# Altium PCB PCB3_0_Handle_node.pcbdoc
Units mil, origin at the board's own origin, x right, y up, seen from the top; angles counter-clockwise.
Board outline 4221.61 x 2402.51 mil, 2 copper layers (Top Layer, Bottom Layer), stack 2.757 mil thick; 43 components, 44 nets, 194 pads, 115 vias.
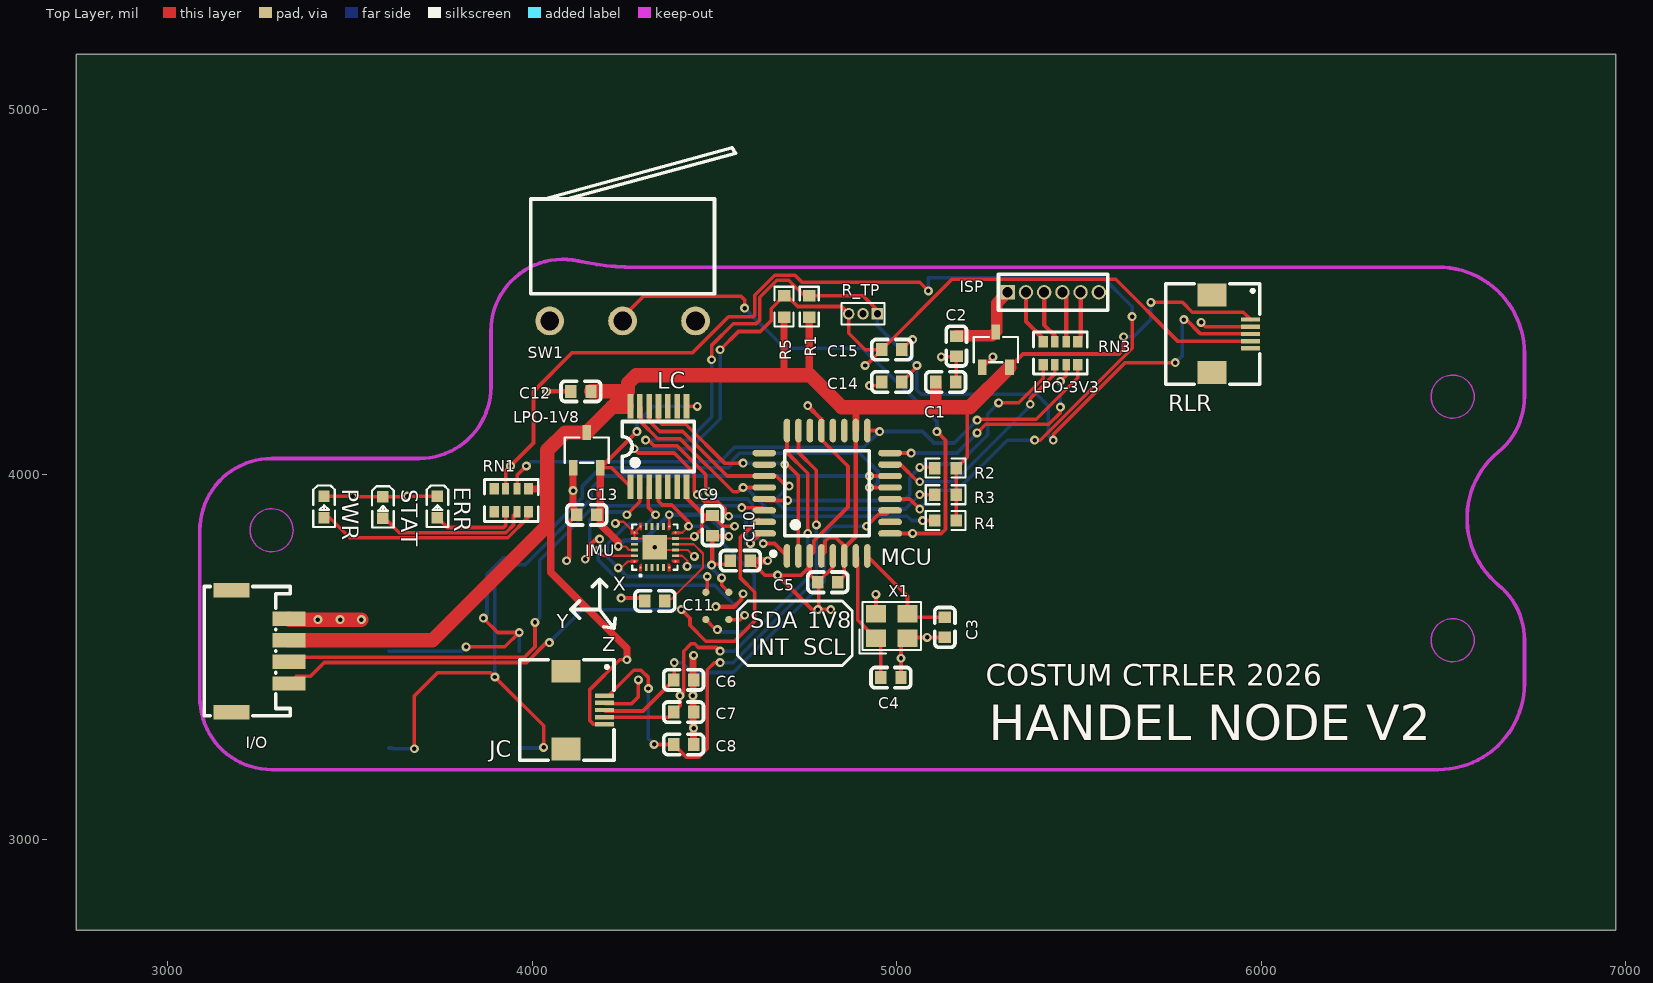
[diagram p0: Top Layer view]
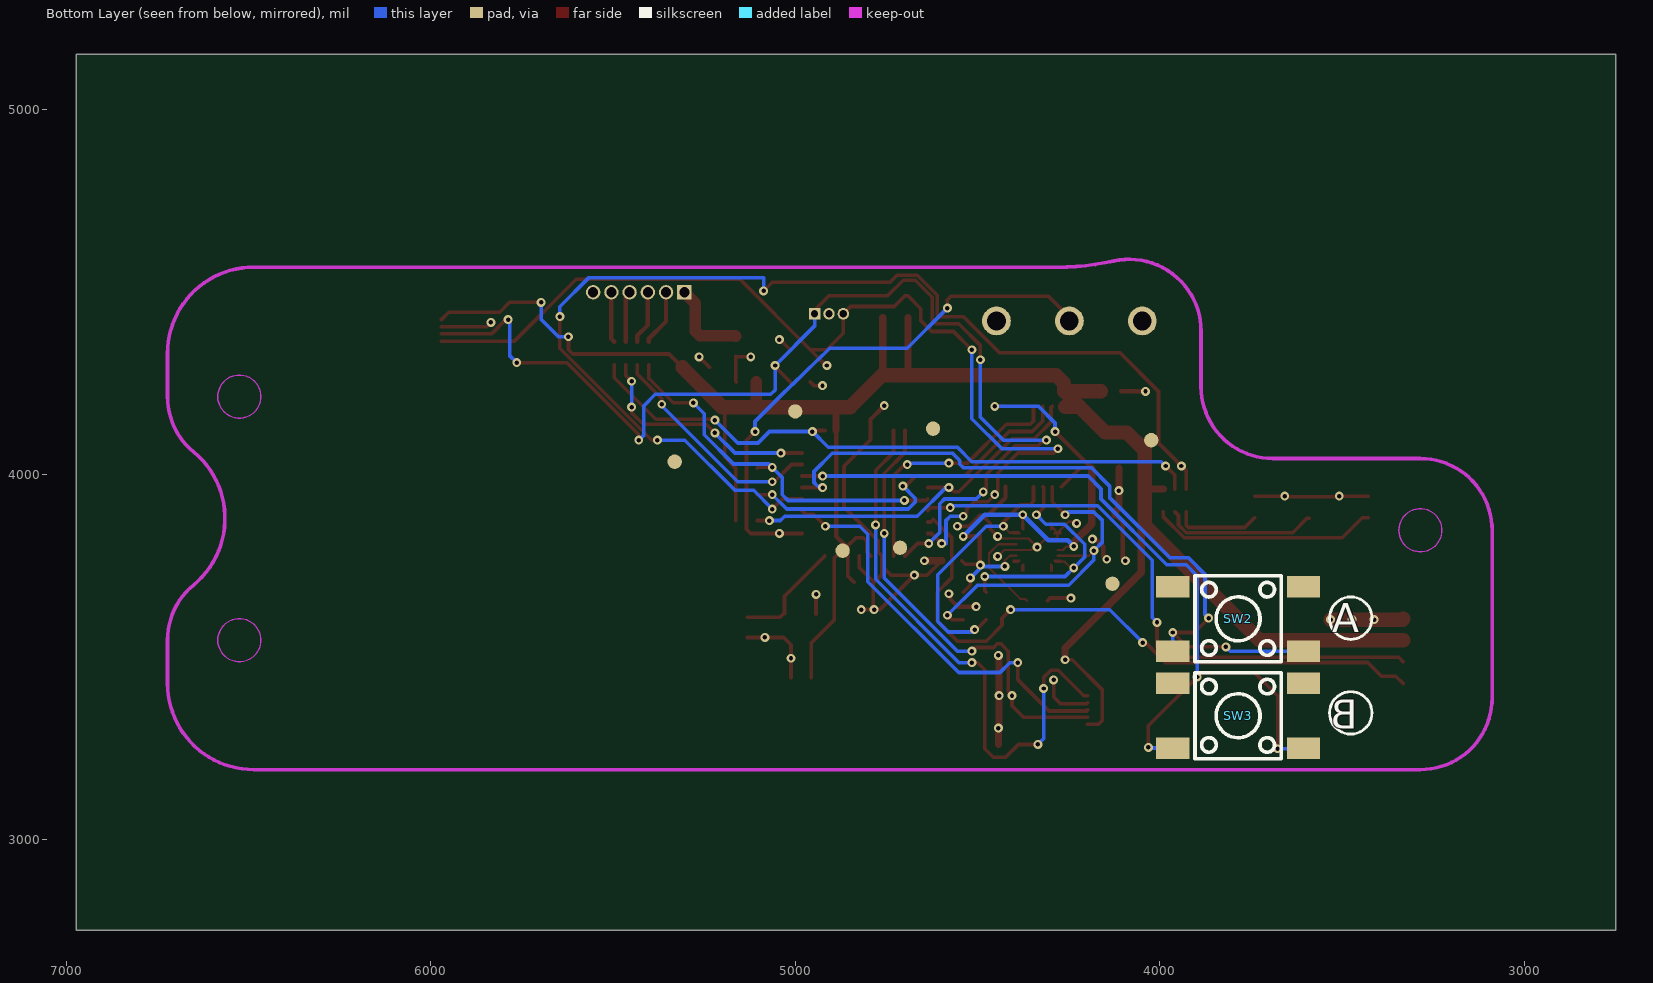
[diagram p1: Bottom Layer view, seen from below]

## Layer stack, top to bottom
Top Solder Mask Layer: solder mask 0.394, Dk 3.3
Top Layer: signal copper 1.379
Bottom Layer: signal copper 1.378
Bottom Solder Mask Layer: solder mask 0.394, Dk 3.3

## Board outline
6971.61,2750 2750,2750 2750,5152.51 6971.61,5152.51

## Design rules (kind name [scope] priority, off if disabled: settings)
BoardOutlineClearance Default [All] p0: genericclearance=10 ignorepadtopadclearanceinfootprint=FALSE except(0: Arc-SplitContinuation Track-SplitContinuation SMDPad-SplitContinuation THPad-SplitContinuation Via-SplitContinuation Fill-SplitContinuation Poly-SplitContinuation Region-SplitContinuation Text-SplitContinuation)
BoardOutlineClearance otherClearance [All] p0: genericclearance=10 ignorepadtopadclearanceinfootprint=FALSE except(0: Arc-SplitContinuation Track-SplitContinuation SMDPad-SplitContinuation THPad-SplitContinuation Via-SplitContinuation Fill-SplitContinuation Poly-SplitContinuation Region-SplitContinuation Text-SplitContinuation)
Clearance Default [All] p1: gap=7 ignorepadtopadclearanceinfootprint=FALSE
Clearance otherClearance [All] p1: gap=7 ignorepadtopadclearanceinfootprint=FALSE
DiffPairsRouting differentialPair [All] p1: maxuncoupledlength=10 minlimit=5 maxlimit=Infinity mostfreqgap=6 toplayer_minwidth=5 toplayer_prefwidth=100 toplayer_maxwidth=100 bottomlayer_minwidth=5 bottomlayer_prefwidth=100 bottomlayer_maxwidth=100
PasteMaskExpansion pasteMaskExpansion [All] p1: expansion=0
PlaneConnect innerPlane [All] p1: planeconnectstyle=Relief reliefexpansion=20 reliefentries=4 reliefconductorwidth=10 reliefairgap=10
PolygonConnect copperRegion [All] p1: connectstyle=Relief reliefentries=4 reliefconductorwidth=10 polygonreliefangle="90 Angle" airgapwidth=10
RoutingVias Default [All] p1: viastyle="Through Hole" holewidth=12.008000000000001 minholewidth=12.008000000000001 maxholewidth=1181 width=12.008000000000001 minwidth=12.008000000000001 maxwidth=1181
SolderMaskExpansion Common [IsVia] p1: useseparateexpansions=TRUE expansion=-1000 expansionbottom=-1000
SolderMaskExpansion Common [All] p2: useseparateexpansions=TRUE expansion=2 expansionbottom=2
Width Default [All] p1: maxlimit=1000 minlimit=6 preferedwidth=6

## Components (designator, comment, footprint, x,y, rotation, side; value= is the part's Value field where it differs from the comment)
1V8 "测试点" 0.5测试点 4476.33,3677.2 r0 top
C1 "1uF" C0603 5133.97,4254 r180 top
C2 "1uF" C0603 5163.5,4352.43 r90 top
C3 "15pf" C0603 5131.73,3580.84 r90 top
C4 "15pf" C0603 4984.09,3443.04 r0 top
C5 "100pf" C0603 4811.02,3704.72 r180 top
C6 "0.1uF" C0603 4415.43,3437.03 r0 top
C7 "0.1uF" C0603 4415.43,3348.44 r0 top
C8 "0.1uF" C0603 4415.43,3259.85 r0 top
C9 "0.1uF" C0603 4494.17,3860.28 r270 top
C10 "0.1uF" C0603 4570.86,3763.78 r0 top
C11 "0.1uF" C0603 4336.69,3653.57 r180 top
C12 "1uF" C0603 4133.86,4228.34 r0 top
C13 "1uF" C0603 4149.67,3889.81 r0 top
C14 "0.1uF" C0603 4986.32,4254 r180 top
C15 "0.1uF" C0603 4986.32,4342.58 r180 top
ERR "GL0603UG01" LED0603-RD 3740.16,3911.41 r270 top
I/O "RX/TX" CONN-SMD_4P-P1.50_ZX-ZH1.5-4PWT 3253.96,3515.77 r270 top
IMU "ICM-20948" QFN-24_L3.0-W3.0-P0.40-BL-EP 4336.69,3801.22 r0 top
INT "测试点" 0.5测试点 4539.33,3602.4 r0 top
ISP "6PIN" HDR-TH_6P-P1.27-V-M 5429.26,4500.07 r0 top
JC "AFC01-S05FCA-00" FPC-SMD_AFC01-S05FCA-00 4145.67,3354.33 r270 top
LC "TXS0104EPWR" TSSOP-14_L5.0-W4.4-P0.65-LS6.4-BL 4346.53,4076.82 r0 top
LPO-1V8 "XC6206P182MR" SOT-23-3_L2.9-W1.6-P1.90-LS2.8-BR 4149.67,4066.98 r270 top
LPO-3V3 "XC6206P332MR" SOT-23-3_L2.9-W1.6-P1.90-LS2.8-BR 5271.77,4342.58 r270 top
MCU "ATMEGA328P-AU" TQFP-32_L7.0-W7.0-P0.80-LS9.0-BL 4809.15,3948.86 r0 top
PWR "GL0603UG01" LED0603-RD 3429.13,3911.42 r270 top
R1 "10kΩ" R0603 4759.94,4460.7 r90 top
R2 "4.7kΩ" R0603 5133.93,4017.8 r0 top
R3 "4.7kΩ" R0603 5133.83,3944.9 r0 top
R4 "4.7kΩ" R0603 5133.83,3874 r0 top
R5 "10kΩ" R0603 4691.03,4460.7 r90 top
R_TP "Roller_Testpoint" HDR-TH_3P-PZ1.0-UP1D-3A 4907.53,4441.04 r180 top
RLR "AFC01-S05FCA-00" FPC-SMD_AFC01-S05FCA-00 5917.32,4385.82 r270 top
RN1 "4.7kΩ" RES-ARRAY-SMD_0603-8P-L3.2-W1.6-BL 3942.97,3929.18 r180 top
RN3 "1kΩ" RES-ARRAY-SMD_0603-8P-L3.2-W1.6-BL 5448.94,4332.74 r0 top
SCL "测试点" 0.5测试点 4476.33,3602.4 r0 top
SDA "测试点" 0.5测试点 4539.33,3677.2 r0 top
STAT "GL0603UG01" LED0603-RD 3590.55,3909.45 r270 top
SW1 "TC-5610D8-T" SW-TH_TC-5610D8-T 4248.1,4421.33 r180 top
SW2 "KH-6X6X10H-STM" SW-SMD_4P-L6.0-W6.0-P4.50-LS9.0-H10.0 3785.53,3604.41 r180 bottom
SW3 "KH-6X6X10H-STM" SW-SMD_4P-L6.0-W6.0-P4.50-LS9.0-H10.0 3785.53,3338.61 r180 bottom
X1 "8MHz" CRYSTAL-SMD_4P-L3.2-W2.5-BL 4986.32,3584.67 r0 top

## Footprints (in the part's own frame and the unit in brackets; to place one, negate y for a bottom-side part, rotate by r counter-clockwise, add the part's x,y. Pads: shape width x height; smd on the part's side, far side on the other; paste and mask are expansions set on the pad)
0.5测试点 [mm]
  round 0.5 smd paste+0 mask+0.051: 1(0,0)
C0603 [mm]
  rect 0.8x0.9 smd paste+0 mask+0.051: 1(-0.7,0) 2(0.7,0)
  silkscreen extent -1.39,-0.71 1.39,0.71
CONN-SMD_4P-P1.50_ZX-ZH1.5-4PWT [mm]
  rect 1x2.3 smd paste+0 mask+0.05: 1(-2.25,2) 2(-0.75,2) 3(0.75,2) 4(2.25,2)
  rect 1x2.5 smd paste+0 mask+0.05: 5(4.25,-2) 6(-4.25,-2)
  silkscreen extent -4.5,-3.9 4.5,2.1
CRYSTAL-SMD_4P-L3.2-W2.5-BL [mm]
  rect 1.4x1.2 smd paste+0 mask+0.051: 1(-1.1,-0.85) 2(1.1,-0.85) 3(1.1,0.85) 4(-1.1,0.85)
  silkscreen extent -2.26,-1.91 2.03,1.68
FPC-SMD_AFC01-S05FCA-00 [mm]
  rect 0.3x1.3 smd paste+0 mask+0.051: 1(-1,1.34) 2(-0.5,1.34) 3(0,1.34) 4(0.5,1.34) 5(1,1.34)
  rect 1.6x2 smd paste+0 mask+0.051: 6(2.7,-1.34) 7(-2.7,-1.34)
  silkscreen extent -3.5,-4.57 3.5,2
HDR-TH_3P-PZ1.0-UP1D-3A [mm]
  rect 0.8x0.8 hole 0.5 paste+0 mask+0.051: 1(-1,0)
  round 0.8 hole 0.5 paste+0 mask+0.051: 2(0,0) 3(1,0)
  silkscreen extent -1.5,-0.75 1.5,0.75
HDR-TH_6P-P1.27-V-M [mm]
  rect 1x1 hole 0.7 paste+0 mask+0.051: 1(-3.175,0)
  round 1 hole 0.7 copper offset 0,0 paste+0 mask+0.051: 2(-1.905,0) 3(-0.635,0) 4(0.635,0) 5(1.905,0) 6(3.175,0)
  silkscreen extent -3.82,-1.25 3.8,1.25
LED0603-RD [mm]
  rect 0.8x0.8 smd paste+0 mask+0.051: 1(-0.749,0) 2(0.749,0)
  silkscreen extent -1.49,-0.75 1.39,0.76
QFN-24_L3.0-W3.0-P0.40-BL-EP [mm]
  round 0.142 smd: 1(-1,-1.428) 6(1,-1.428) 7(1.428,-1) 12(1.428,1) 13(1,1.428) 18(-1,1.428) 19(-1.428,1) 24(-1.428,-1)
  rect 0.2x0.505 smd paste-100 mask+0.051: 2(-0.6,-1.428) 3(-0.2,-1.428) 4(0.2,-1.428) 5(0.6,-1.428) 14(0.6,1.428) 15(0.2,1.428) 16(-0.2,1.428) 17(-0.6,1.428)
  rect 0.505x0.2 smd paste-100 mask+0.051: 8(1.428,-0.6) 9(1.428,-0.2) 10(1.428,0.2) 11(1.428,0.6) 20(-1.428,0.6) 21(-1.428,0.2) 22(-1.428,-0.2) 23(-1.428,-0.6)
  rect 1.7x1.7 smd paste-100 mask+0.051: 25(0,0)
  Top Layer region: -1.1,1.68 -0.9,1.68 -0.9,1.175 -1,1.174 -1.1,1.274
  Top Layer region: -1.68,-1.1 -1.274,-1.1 -1.174,-1 -1.175,-0.9 -1.68,-0.9
  Top Layer region: 1.68,-1.1 1.275,-1.1 1.175,-1 1.175,-0.9 1.68,-0.9
  Top Layer region: 1.68,1.1 1.274,1.1 1.174,1 1.175,0.9 1.68,0.9
  Top Layer region: 1.1,1.68 0.9,1.68 0.9,1.175 1,1.174 1.1,1.274
  Top Layer region: -1.1,-1.68 -0.9,-1.68 -0.9,-1.175 -1,-1.174 -1.1,-1.275
  Top Layer region: 1.1,-1.68 0.9,-1.68 0.9,-1.175 1,-1.175 1.1,-1.275
  Top Layer region: -1.68,1.1 -1.274,1.1 -1.174,1 -1.175,0.9 -1.68,0.9
  silkscreen extent -1.58,-2.05 1.58,1.58
R0603 [mil]
  rect 31.75x34.02 smd paste-3937.01 mask+2: 1(-29.65,0) 2(29.65,0)
  silkscreen extent -55,-26 55,26
RES-ARRAY-SMD_0603-8P-L3.2-W1.6-BL [mm]
  rect 0.65x0.8 smd paste+0 mask+0.051: 1(-1.2,-0.8) 4(1.2,-0.8) 5(1.2,0.8) 8(-1.2,0.8)
  rect 0.5x0.8 smd paste+0 mask+0.051: 2(-0.4,-0.8) 3(0.4,-0.8) 6(0.4,0.8) 7(-0.4,0.8)
  silkscreen extent -1.87,-1.45 1.87,1.47
SOT-23-3_L2.9-W1.6-P1.90-LS2.8-BR [mm]
  rect 1.07x0.6 smd paste+0 mask+0.051: 1(1.235,-0.95) 2(1.235,0.95) 3(-1.235,0)
  silkscreen extent -0.88,-1.54 0.88,1.54
SW-SMD_4P-L6.0-W6.0-P4.50-LS9.0-H10.0 [mm]
  rect 2.3x1.5 smd paste+0 mask+0.051: 1(-4.55,2.25) 2(4.55,2.25) 3(-4.55,-2.25) 4(4.55,-2.25)
  silkscreen extent -3,-3 3,3
SW-TH_TC-5610D8-T [mm]
  round 2 hole 1.3 paste+0 mask+0.051: 1(5.08,0) 2(-5.08,0) 3(0,0)
  Top Layer circle w0.55: c5.08,0 r0.275
  Top Layer circle w0.55: c-5.08,0 r0.275
  Top Layer circle w0.55: c0,0 r0.275
  silkscreen extent -7.87,-12.07 6.4,-1.9
TQFP-32_L7.0-W7.0-P0.80-LS9.0-BL [mm]
  oval 0.45x1.65 smd paste+0 mask+0.051: 1(-2.8,-4.369) 2(-2,-4.369) 3(-1.2,-4.369) 4(-0.4,-4.369) 5(0.4,-4.369) 6(1.2,-4.369) 7(2,-4.369) 8(2.8,-4.369) 17(2.8,4.369) 18(2,4.369) 19(1.2,4.369) 20(0.4,4.369) 21(-0.4,4.369) 22(-1.2,4.369) 23(-2,4.369) 24(-2.8,4.369)
  oval 1.65x0.45 smd paste+0 mask+0.051: 9(4.381,-2.8) 10(4.381,-2) 11(4.381,-1.2) 12(4.381,-0.4) 13(4.381,0.4) 14(4.381,1.2) 15(4.381,2) 16(4.381,2.8) 25(-4.381,2.8) 26(-4.381,2) 27(-4.381,1.2) 28(-4.381,0.4) 29(-4.381,-0.4) 30(-4.381,-1.2) 31(-4.381,-2) 32(-4.381,-2.8)
  silkscreen extent -3.91,-4.36 2.94,2.95
TSSOP-14_L5.0-W4.4-P0.65-LS6.4-BL [mm]
  rect 0.4x1.7 smd paste+0 mask+0.051: 1(-1.95,-2.8) 2(-1.3,-2.8) 3(-0.65,-2.8) 4(0,-2.8) 5(0.65,-2.8) 6(1.3,-2.8) 7(1.95,-2.8) 8(1.95,2.8) 9(1.3,2.8) 10(0.65,2.8) 11(0,2.8) 12(-0.65,2.8) 13(-1.3,2.8) 14(-1.95,2.8)
  silkscreen extent -2.51,-1.74 2.5,1.74

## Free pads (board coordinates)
  round 39.37 smd far side paste+0 mask+2: 2(4023.62,4094.49) 2(4129.92,3700.79) 2(4622.04,4125.98) 2(4712.6,3799.21) 2(4870.07,3791.34) 2(5000,4173.23) 2(5330.7,4035.43)

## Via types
v1: diameter 24.41, hole 12.2, Top Layer to Bottom Layer, 115 vias

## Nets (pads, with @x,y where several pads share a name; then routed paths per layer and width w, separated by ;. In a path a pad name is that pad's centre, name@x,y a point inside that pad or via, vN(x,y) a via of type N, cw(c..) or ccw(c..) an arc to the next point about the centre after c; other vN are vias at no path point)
1V8: C9.2 C10.1 C13.2 IMU.8 IMU.13 IMU.22 LC.1 LC.8 LPO-1V8.2 SDA.1 | length 1553.8
  Top Layer w5.98: v1@4236.23,3803.1 4255.93,3803.1 4265.73,3793.3 IMU.22 ; IMU.13 v1(4376.06,3889.76) ; IMU.8 4411.37,3777.59 4425.2,3763.77 v1(4425.2,3748.03)
  Top Layer w10: LC.1 4217.98,4018.36 LPO-1V8.2 4187.64,4018.35 v1(4287.4,4118.11) ; LC.8 v1(4452.76,4187.07) ; v1(4492.13,3751.97) 4493.93,3753.78 4533.31,3753.78 C10.1 ; v1(4519.69,3716.53) 4519.69,3696.84 SDA.1@4539.37,3677.16
  Top Layer w11.81: C9.2 4496.18,3830.71 v1(4539.37,3830.71) ; v1@4494.23,3752.7 C9.2
  Top Layer w19.68: LPO-1V8.2@4187.03,4018.4 4187.03,3864.1 4236.23,3815 v1@4236.23,3803.1
  Bottom Layer w10: v1(4287.4,4118.11) 4287.43,4141.7 4332.73,4187.1 v1@4452.73,4187.1
  Bottom Layer w11.81: v1@4236.22,3803.15 4252.83,3819.76 4306.06,3819.76 v1(4376.06,3889.76) 4480.31,3889.76 v1(4539.37,3830.71) ; v1(4425.2,3748.03) 4488.19,3748.03 v1(4519.69,3716.53)
  other v1: 4236.22,3803.15
3V3: C1.2 C5.1 C12.2 I/O.2 JC.5 LC.14 LPO-1V8.3 LPO-3V3.2 MCU.4 MCU.6 MCU.18 R1.1 R2.2 R3.2 R4.2 R5.1 RLR.1 RN1.1 | length 5572.8
  Top Layer w10: JC.5 4168.43,3315 4158.43,3325 4158.43,3410.4 4240.13,3492.1 v1(4259.84,3492.12) ; MCU.4 4803.4,3786.87 4803.4,3816.87 4813.4,3826.87 4833.4,3826.87 4856.4,3803.88 MCU.6 4856.39,3722.54 C5.1 ; R3.2@5163.47,3944.84 R2.2@5163.66,4017.74 ; R4.2 R3.2 ; R2.2 5193.62,4047.77 5193.62,4178.4 5200.27,4185.04 ; LPO-3V3.2 5346.43,4330.7 5609.94,4330.7 5622.03,4342.79 v1@5622.03,4377.9 ; v1(5696.85,4472.44) 5783.47,4472.44 5810.71,4445.19 5950.07,4445.19 RLR.1
  Top Layer w11.81: MCU.6 4857.89,3778.36 4857.89,3800.86 4887.89,3830.86 MCU.18
  Top Layer w19.68: RN1.1 4041.36,3960.67 ; 4041.32,3860.2 4051.23,3860.2 4051.23,3732.3 4259.84,3523.69 v1(4259.84,3492.12) ; R5.1 4691.03,4282.26 4700.88,4272.41 ; R1.1 4759.94,4274.69 4762.21,4272.41 ; MCU.18 4887.89,4185.14
  Top Layer w31.5: 5106.41,4185.1 C1.2
  Top Layer w39.37: I/O.2 3726.47,3545.34 4041.36,3860.24 4041.36,4066.94 4091.16,4115.64 LPO-1V8.3 ; LPO-1V8.3 4219.67,4185.6 4259.67,4185.6 ; C12.2 4263.03,4229 ; 4219.66,4185.64 4263.06,4229.04 4263.06,4250.74 4284.77,4272.44 4762.16,4272.44 4849.56,4185.04 5200.27,4185.04 LPO-3V3.2@5309.16,4293.94
  Bottom Layer w10: v1@5622.05,4377.95 5649.6,4377.95 5696.85,4425.19 v1(5696.85,4472.44)
  other v1: 5622.05,4377.95
ERR_2: ERR.2 RN1.6 | length 238
  Top Layer w10: ERR.2 3767.28,3854.8 3921.87,3854.8 3927.22,3860.15 RN1.6
GND: C1.1 C2.1 C3.1 C4.2 C5.2 C6.2 C7.2 C8.2 C9.1 C10.2 C11.2 C12.1 C13.1 C14.2 C15.1 ERR.1 I/O.1 IMU.9 IMU.11 IMU.18 IMU.19 IMU.20 IMU.25 ISP.6 JC.2 LC.7 LPO-1V8.1 LPO-3V3.1 MCU.3 MCU.5 MCU.21 pad.2 PWR.1 R_TP.2 RLR.2 STAT.1 SW1.1 SW2.2 SW3.1 SW3.2 X1.2 X1.4 | length 4020.8
  Top Layer w5.98: v1(4228.35,3866.14) 4232.79,3870.59 4250.48,3870.59 IMU.19 ; IMU.18 IMU.19 ; IMU.9 4427.16,3793.34 v1(4444.88,3775.59) ; v1(4444.88,3830.71) 4439.01,3824.84 IMU.11 4360.31,3824.84 v1(4336.69,3801.22) 4313.06,3824.84 IMU.20 IMU.19
  Top Layer w6.3: v1(4336.69,3801.22) 4345.02,3801.22 4352.89,3793.35 IMU.9
  Top Layer w10: PWR.1 3507.83,3940.9 3509.85,3938.93 3590.55,3938.93 3655.47,3938.93 v1(3657.48,3940.94) ; v1(3657.48,3940.94) ERR.1@3740.13,3940.9 ; JC.2 4201.19,3371.24 4272.81,3371.24 4291.33,3389.75 v1(4291.34,3437.01) ; v1(4244.1,3661.42) 4301.28,3661.42 C11.2@4309.17,3653.53 ; v1(4444.88,3830.71) 4464.93,3850.7 4464.93,3866.5 4486.23,3887.8 C9.1 ; C9.1 4523.74,3858.27 v1(4555.12,3858.27) ; C10.2 4637.79,3724.41 v1(4673.23,3724.41) ; MCU.3 4771.93,3786.9 4771.93,3816.9 4866.13,3911.1 4866.13,4022.6 4793.43,4095.4 MCU.21 ; v1(4818.9,3629.92) v1(4783.47,3629.92) ; MCU.5 4824.9,3746.17 C5.2@4783.46,3704.72 ; v1(4925.2,4244.09) 4948.86,4244.09 C14.2 ; C4.2@5011.65,3443.05 v1(5011.65,3496.41) 5011.65,3533.23 X1.2 5031.7,3553.29 v1(5083.45,3553.29) C3.1 ; C15.1 5041.38,4370.08 v1(5043.31,4370.08) ; v1(5122.05,4322.83) 5161.46,4322.83 C2.1 5163.49,4255.97 C1.1 ; LPO-3V3.1 5263.24,4322.83 v1(5263.78,4322.83) ; v1(5834.64,4417.32) 5846.45,4405.5 RLR.2 ; v1(4673.23,3724.41) 4737.8,3724.41 4757.8,3744.41 4757.8,3772.74 MCU.3 4761.92,3726.26 C5.2@4783.46,3704.72 ; v1(4673.23,3724.41) 4767.73,3629.9 v1@4783.43,3629.9 ; v1(4783.47,3629.92) 4785.59,3632.05 4785.59,3702.59 C5.2@4783.46,3704.72
  Top Layer w11.81: I/O.1 I/O.1@3334.64,3606.3 ; v1(4039.37,4228.34) C12.1 ; v1(4094.49,3763.78) 4102.11,3771.41 4102.11,3869.81 C13.1 ; v1(4145.67,3767.71) 4155.04,3777.09 4155.04,3802.83 4175.04,3822.83 v1(4185.04,3822.83) ; LC.7 4423.3,3936.59 4472.05,3887.84 C9.1 ; v1(4503.94,3637.79) 4553.93,3637.79 4573.93,3657.79 4573.93,3668.42 v1(4578.74,3673.23) ; v1(4755.91,4188.97) 4793.4,4151.47 MCU.21 ; X1.4 v1(4943.02,3671.36)
  Top Layer w19.68: LPO-1V8.1 v1(4112.27,3956.13) 4112.27,3908.36 4122.11,3898.51 C13.1 ; C8.2@4442.98,3259.86 v1(4442.99,3304.83) 4440.95,3306.87 v1(4440.95,3393.7) 4440.93,3503.9 v1(4442.99,3503.93) ; C10.2 v1(4645.67,3763.78)
  Top Layer w39.37: I/O.1 3334.69,3602.36 v1(3412.14,3602.36) v1(3473.57,3602.36) v1(3531.5,3602.36)
  other v1: 3507.88,3940.94
IMU_10: C11.1 IMU.10 | length 267
  Top Layer w5.98: C11.1 4369.73,3659.1 4382.93,3659.1 4468.53,3744.7 4468.53,3783.5 4442.93,3809.1 IMU.10
INT_1V8: IMU.12 LC.4 SCL.1 | length 723.4
  Top Layer w5.98: IMU.12 4411.45,3840.59 v1(4429.14,3858.26)
  Top Layer w10: LC.4@4346.46,3966.53 4346.46,3926.67 4356.53,3916.6 4382.63,3916.6 4429.13,3870.1 v1(4429.14,3858.26) ; SCL.1@4476.38,3602.36 4503.94,3574.8 v1(4507.87,3574.8)
  Bottom Layer w10: v1(4429.14,3858.26) 4476.38,3858.26 4609.13,3725.51 4609.13,3597.32 4580.07,3568.26 4514.4,3568.26 v1(4507.87,3574.8)
INT_20948: LC.11 MCU.2 | length 705.8
  Top Layer w10: LC.11@4346.53,4187 4346.53,4147 4355.73,4137.8 4421.23,4137.8 4527.53,4031.5 v1(4578.74,4031.49) ; v1@4692.83,4027.5 4700.33,4026.8 4730.33,3996.8 MCU.2@4730.33,3776.8
  Bottom Layer w10: v1(4578.74,4031.49) 4688.91,4031.5 v1(4692.87,4027.54)
ISP_2: ISP.2 RN3.8 | length 155.5
  Top Layer w11.81: ISP.2 5354.26,4420.08 5401.7,4372.63 RN3.8
ISP_3: ISP.3 RN3.7 | length 147.8
  Top Layer w11.81: ISP.3 5404.26,4410.08 5433.19,4381.14 RN3.7
ISP_4: ISP.4 RN3.6 | length 140.2
  Top Layer w11.81: ISP.4 5464.69,4489.64 RN3.6
ISP_5: ISP.5 RN3.5 | length 139.2
  Top Layer w11.81: RN3.5 5504.26,4372.31 ISP.5
JC_SW: C6.1 JC.3 MCU.11 | length 1138.5
  Top Layer w10: JC.3 4201.21,3351.55 4304.3,3351.55 4387.88,3435.12 C6.1 4389.76,3438.91 v1@4389.76,3484.25 ; v1(4917.32,3858.27) 4950.67,3891.63 4971.66,3891.63 MCU.11@4981.66,3901.63
  Bottom Layer w10: v1@4389.73,3484.3 4411.83,3484.3 4438.73,3457.3 4551.83,3457.3 4800.93,3706.4 4800.93,3836.4 4822.83,3858.3 v1(4917.32,3858.27)
  other v1: 4389.77,3484.25
JC_X: C8.1 JC.1 MCU.23 | length 1565.2
  Top Layer w10: JC.1 4208.63,3393.7 4278.63,3463.7 4298.43,3463.7 4318.93,3443.2 v1(4318.9,3413.39) ; v1(4334.64,3259.84) C8.1 ; C8.1@4387.83,3259.9 4423.33,3224.4 4456.73,3224.4 4480.33,3248 4480.33,3464.6 4500.03,3484.3 v1@4515.73,3484.3 ; MCU.23 4730.43,4060.9 4779.53,4011.8 v1(4779.53,3862.2)
  Bottom Layer w10: v1(4318.9,3413.39) 4318.9,3275.59 v1(4334.64,3259.84) ; v1(4515.75,3484.25) 4551.18,3484.25 4779.52,3712.6 v1(4779.53,3862.2)
JC_Y: C7.1 JC.4 MCU.24 | length 1241.9
  Top Layer w10: JC.4 4374.08,3334.64 C7.1 ; C7.1 4405.51,3366.08 v1(4405.51,3393.7) 4415.74,3403.94 4415.74,3515.75 4435.74,3535.75 4445.74,3535.75 4455.74,3525.75 4505.74,3525.75 v1@4515.74,3515.75 ; MCU.24 4698.91,4060.87 4755.91,4003.87 v1(4755.91,3838.58)
  Bottom Layer w10: v1(4515.75,3515.75) 4555.12,3515.75 4755.91,3716.54 v1(4755.91,3838.58)
LED_STAT: MCU.12 RN1.3 | length 3163.6
  Top Layer w10: RN1.3 3927.22,4009.89 v1(3940.95,4023.62) 4003.87,4086.55 4003.87,4228.15 4110.37,4334.65 4440.76,4334.65 4538.81,4432.68 4605.91,4432.68 4610.23,4437 4610.23,4492.12 4665.11,4547 4720.7,4547 4740.15,4527.56 5062.98,4527.56 v1(5086.61,4503.93) ; MCU.12@4981.66,3933.11 5035.38,3933.11 v1(5062.99,3905.51) ; v1(5377.95,4094.49) 5393.64,4094.5 5645.63,4346.59 v1@5645.63,4433.1
  Bottom Layer w10: v1(5062.99,3905.51) 5114.13,3956.7 5165.33,3956.7 5303.13,4094.5 v1(5377.95,4094.49) ; v1(5086.61,4503.93) 5086.63,4539.4 5566.93,4539.4 5645.67,4460.66 v1(5645.67,4433.07)
MISO: MCU.16 RN3.3 | length 651.3
  Top Layer w10: MCU.16@4981.65,4059.11 v1(5039.37,4059.11) ; v1(5220.43,4114.2) 5244.02,4137.79 5417.12,4137.79 5448.82,4169.49 v1(5448.82,4185.04) ; v1(5448.82,4255.9) 5464.69,4271.78 RN3.3
  Bottom Layer w10: v1@5039.33,4059.1 5165.33,4059.1 v1(5220.43,4114.2) ; v1(5448.82,4185.04) v1(5448.82,4255.9)
MOSI: MCU.15 RN3.2 | length 630.5
  Top Layer w10: MCU.15@4981.66,4027.61 5010.5,4027.61 5057.8,3980.31 v1(5062.99,3980.31) ; v1(5366.14,4192.91) 5366.14,4208.66 5433.19,4275.72 RN3.2
  Bottom Layer w10: v1(5062.99,3980.31) 5157.42,3980.3 5366.14,4189.01 v1(5366.14,4192.91)
PWR_2: PWR.2 RN1.8 | length 621.6
  Top Layer w10: PWR.2 3444.73,3881.9 3499.83,3826.8 3933.47,3826.8 3990.23,3883.56 RN1.8
ROLLER_A: C14.1 MCU.1 R1.2 R_TP.1 RLR.3 | length 3155.1
  Top Layer w10: v1(4311.03,4094.49) 4318.93,4094.5 4334.63,4078.7 4397.63,4078.7 4476.33,4000 4476.33,3960.6 v1(4484.25,3952.75) ; v1(4492.13,4314.96) 4492.13,4354.3 4551.23,4413.4 4614.23,4413.4 4624.23,4423.4 4624.23,4486.4 4670.83,4533 4704.12,4533 4746.73,4490.4 R1.2 ; v1(4633.86,3811.02) 4664.76,3811.02 MCU.1 ; R1.2 4907.59,4490.36 4946.9,4451.04 R_TP.1 ; C14.1 5055.12,4295.23 v1(5055.12,4299.21) ; v1(5429.13,4094.49) 5429.13,4110.19 5626.02,4307.08 v1(5763.78,4307.08) ; v1(5787.4,4425.19) 5793.95,4425.19 5833.32,4385.82 RLR.3
  Bottom Layer w10: v1(4311.03,4094.49) 4429.14,4094.49 4492.13,4157.48 v1(4492.13,4314.96) ; v1@4484.23,3952.7 4503.93,3933.1 4590.53,3933.1 4603.83,3919.8 4603.83,3841 v1@4633.83,3811 ; R_TP.1 4946.9,4407.42 v1(5055.12,4299.21) 5055.12,4232.3 5066.95,4220.47 5383.85,4220.47 5415.12,4189.2 5415.12,4108.49 v1(5429.13,4094.49) ; v1(5763.78,4307.08) 5783.43,4326.8 5783.43,4421.22 v1(5787.4,4425.19)
ROLLER_B: C15.2 MCU.32 R5.2 R_TP.3 RLR.4 | length 2848.7
  Top Layer w10: v1(4279.53,4070.86) 4291.34,4059.05 4389.73,4059.1 4444.93,4003.9 4444.93,3952.8 4452.73,3944.9 4471.81,3925.82 4509.37,3925.82 4529.37,3905.82 4529.37,3895.82 v1(4539.37,3885.82) ; v1(4515.75,4342.52) 4565.74,4392.52 4625.74,4392.52 4655.74,4422.52 4655.74,4455.07 R5.2 4698.85,4490.36 4728.16,4461.04 4848.16,4461.04 R_TP.3 ; v1(4598.43,3811.02) 4626.03,3838.62 MCU.32@4636.66,3838.62 ; R_TP.3@4868.13,4441 4868.13,4387.7 4913.33,4342.6 C15.2@4958.73,4342.6 ; v1(4913.39,4299.21) 4915.39,4299.21 C15.2 ; RLR.4 5770.07,4366.13 5600.81,4535.4 5151.63,4535.4 C15.2@4958.73,4342.6
  Bottom Layer w10: v1(4279.53,4070.86) 4433.03,4070.9 4515.73,4153.5 v1(4515.75,4342.52) ; v1@4539.33,3885.8 4574.83,3885.8 4586.63,3874 4586.63,3811 v1(4598.43,3811.02)
  other v1: 4452.76,3944.88
RST: MCU.29 R2.1 RN3.1 | length 1046.3
  Top Layer w10: MCU.29@4636.65,3933.11 4640.64,3929.13 v1(4700.79,3929.13) ; v1(5062.99,4019.68) 5102.4,4019.68 R2.1 ; v1(5279.53,4196.85) 5334.53,4196.85 5401.73,4264.05 RN3.1
  Bottom Layer w10: v1(4700.79,3929.13) 5019.73,3929.1 5035.43,3944.9 5035.43,3992.1 v1(5062.99,4019.68) ; v1(5062.99,4019.68) 5072.28,4028.97 5169.52,4028.97 5249.52,4108.98 5249.52,4166.85 v1(5279.53,4196.85)
RX: I/O.3 MCU.30 | length 1618.2
  Top Layer w10: I/O.3@3332.66,3486.24 3345.16,3498.74 3979.07,3498.74 4007.86,3527.54 v1@4007.86,3594.44 ; v1(4574.8,3909.45) 4628.85,3909.45 MCU.30@4636.67,3901.64
  Bottom Layer w10: v1@4007.82,3594.4 4021.23,3607.9 4021.23,3765.3 4170.32,3914.5 4569.75,3914.5 v1(4574.8,3909.45)
  other v1: 4007.88,3594.49
S$13491: 
S$23486: 
S$23490: 
S$23494: 
S$23502: 
S$23506: 
S$23513: 
S$23520: 
S$23524: 
SCK: MCU.17 RN1.2 RN3.4 | length 1782.2
  Top Layer w10: RN1.2 3958.71,3998.09 v1(3984.25,4023.62) ; v1@5220.43,4149.6 5222.64,4151.79 5382.75,4151.79 5496.23,4265.27 RN3.4@5496.23,4301.2
  Top Layer w11.81: MCU.17 4949.99,4120.87 v1(4952.76,4118.11)
  Bottom Layer w10: v1(3984.25,4023.62) 3996.03,4035.4 4515.73,4035.4 4555.13,4074.8 4909.43,4074.8 4952.73,4118.1 5070.93,4118.1 5102.33,4086.6 5157.43,4086.6 v1@5220.43,4149.6
  other v1: 5220.47,4149.6
SCL: LC.13 MCU.28 R4.1 | length 1028.6
  Top Layer w10: LC.13@4295.33,4187 4298.73,4184 4298.73,4144 4344.33,4098.4 4405.63,4098.4 4551.23,3952.8 4563.03,3952.8 v1(4578.74,3964.56) ; v1(4578.74,3964.56) MCU.28 MCU.28@4636.67,3964.64 ; v1(5070.87,3874.01) R4.1
  Bottom Layer w10: v1(4578.74,3964.56) 4586.63,3964.6 4665.43,3885.8 5029.03,3885.8 5040.83,3874 v1@5070.83,3874
SCL_1V8: IMU.23 INT.1 LC.2 | length 942.6
  Top Layer w5.98: v1(4181.1,3791.34) 4194.84,3777.59 IMU.23
  Top Layer w10: v1(4259.85,3889.76) 4295.28,3925.2 LC.2@4295.28,3966.52 ; INT.1@4539.37,3602.36 4570.92,3602.36 v1(4582.77,3614.21)
  Bottom Layer w10: v1(4181.1,3791.34) 4181.1,3765.87 4250.11,3696.85 4500.11,3696.85 v1(4582.77,3614.21) ; v1(4181.1,3791.34) 4157.53,3814.9 4157.53,3874 4181.13,3897.6 4252.03,3897.6 v1(4259.85,3889.76)
SDA: LC.12 MCU.27 R3.1 | length 1013.2
  Top Layer w10: LC.12@4320.93,4187 4320.93,4147 4349.83,4118.1 4413.33,4118.1 4535.33,3996.1 MCU.27 4669.23,3996.1 4696.83,3968.5 v1(4704.73,3968.5) ; v1(5062.99,3944.88) R3.1
  Bottom Layer w10: v1(4704.73,3968.5) 4670.83,3934.6 4670.83,3924.8 4690.13,3905.5 5023.63,3905.5 v1(5062.99,3944.88)
SDA_1V8: 1V8.1 IMU.24 LC.3 | length 679.2
  Top Layer w5.98: v1(4236.22,3744.09) 4244.13,3744.1 4261.83,3761.8 IMU.24
  Top Layer w10: LC.3 4318.9,3964.55 4318.9,3909.44 v1(4338.58,3889.76) ; 1V8.1@4476.38,3677.16 4480.31,3681.1 v1(4480.32,3720.47)
  Bottom Layer w10: v1(4236.22,3744.09) 4206.23,3774.1 4206.23,3808.6 4261.73,3864.1 4312.93,3864.1 v1(4338.58,3889.76) ; v1@4236.27,3744.14 4259.93,3720.47 v1(4480.32,3720.47)
STAT_2: RN1.7 STAT.2 | length 423.1
  Top Layer w10: STAT.2@3590.55,3879.95 3596.45,3879.95 3635.6,3840.8 3927.67,3840.8 3948.71,3861.85 3948.71,3887.69 RN1.7
SW1: MCU.9 SW1.3 | length 1477.8
  Top Layer w10: SW1.3@4265.64,4449.69 4305.32,4489.38 4572.68,4489.38 4582.68,4479.38 v1(4582.68,4456.69) ; MCU.9@4981.66,3838.54 v1(5043.27,3838.54) ; v1@5043.23,3838.5 5122.03,3838.5 5133.83,3850.4 5133.85,4094.49 v1(5110.24,4118.11)
  Bottom Layer w10: v1@4582.63,4456.7 4692.93,4346.5 4905.53,4346.5 ; 4905.51,4346.45 5043.27,4212.64 5110.23,4145.67 v1(5110.24,4118.11)
SW2: MCU.13 SW2.3 SW2.4 | length 2040.2
  Top Layer w10: v1(3818.9,3527.56) 3925.19,3527.56 v1(3964.57,3566.93) 3905.51,3566.93 v1(3866.15,3606.3) ; v1(4925.17,3964.54) MCU.13@4981.66,3964.64
  Bottom Layer w10: SW2.4@3606.34,3515.78 3807.12,3515.78 v1(3818.9,3527.56) ; v1(3866.15,3606.3) 3876.13,3616.3 3876.13,3726.3 3921.53,3771.7 3972.43,3771.7 4137.83,3937 4137.83,3968.5 4187.63,4018.4 4538.63,4018.4 4548.63,4028.4 4548.63,4038.4 4568.63,4058.4 4898.63,4058.4 4948.63,4008.4 4948.63,3978.4 4938.63,3968.4 4929.03,3968.4 v1@4925.13,3964.5 ; SW2.3@3964.6,3515.78 v1(3964.57,3566.93)
SW3: MCU.14 SW3.3 SW3.4 | length 2276
  Top Layer w10: v1@3677.13,3248 3677.13,3393.7 3740.13,3456.7 3885.82,3456.69 v1(3897.64,3444.88) 4031.5,3311.02 v1(4031.5,3251.97) ; v1(4925.17,3996.04) MCU.14@4981.66,3996.14
  Bottom Layer w10: SW3.4@3606.34,3250.02 3615.18,3250.02 3617.16,3248.03 v1(3677.17,3248.03) ; v1(3897.64,3444.88) 3897.64,3722.51 3903.53,3728.4 3927.83,3752.8 3981.13,3752.8 4161.43,3933 4161.43,3960.7 4196.73,3996 v1@4925.13,3996 ; SW3.3@3964.61,3250.02 4029.54,3250.02 v1(4031.5,3251.97)
TOSC1: C4.1 MCU.7 X1.1 | length 362.3
  Top Layer w10: MCU.7 4893.01,3771.74 4893.01,3601.21 X1.1 4956.53,3537.69 C4.1
TOSC2: C3.2 MCU.8 X1.3 | length 310.5
  Top Layer w10: MCU.8 5029.63,3666.62 X1.3 5032,3618.14 5041.73,3608.4 C3.2
TX: I/O.4 MCU.31 | length 1766
  Top Layer w10: I/O.4 3352.73,3447.2 3392.03,3447.2 3429.56,3484.74 3984.86,3484.74 4039.53,3539.4 v1(4047.25,3539.37) ; v1(4409.45,3629.92) 4433.03,3606.3 4433.03,3586.6 4476.33,3543.3 4555.13,3543.3 4610.23,3598.5 4610.23,3677.1 4571.23,3716.1 4571.23,3827.4 4621.23,3877.4 4628.53,3870.1 MCU.31
  Bottom Layer w10: v1(4047.25,3539.37) 4137.24,3629.37 4408.9,3629.37 v1(4409.45,3629.92)
VCC: C2.2 ISP.1 LPO-3V3.3 | length 235.2
  Top Layer w31.5: C2.2 5164.72,4381.21 5261.77,4381.21 LPO-3V3.3 5274.26,4393.7 5274.26,4470.07 ISP.1
pads on no net: I/O.5 I/O.6 IMU.1 IMU.2 IMU.3 IMU.4 IMU.5 IMU.6 IMU.7 IMU.14 IMU.15 IMU.16 IMU.17 IMU.21 JC.6 JC.7 LC.5 LC.6 LC.9 LC.10 MCU.10 MCU.19 MCU.20 MCU.22 MCU.25 MCU.26 RLR.5 RLR.6 RLR.7 RN1.4 RN1.5 SW1.2 SW2.1

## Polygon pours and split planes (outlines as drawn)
GND on Bottom Layer (solid, remove dead copper, pour order 8): 6066.92,4712.6 6066.92,4275.59 5838.58,4047.24 5606.29,4047.24 5311.02,3751.97 5311.02,3043.31 5271.65,3003.94 3122.05,3000 3000,3122.05 3000,4724.41 3169.29,4893.7

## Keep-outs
Board Outline Layer:
  region: 6583.82,4213.94 cw(c6524.77,4213.94) 6465.71,4213.94 cw(c6524.77,4213.94)
  circle w0.1: c6524.77,4213.94 r59.05
  region: 6583.82,4213.94 cw(c6524.77,4213.94) 6465.71,4213.94 cw(c6524.77,4213.94)
  region: 6583.82,3545.81 cw(c6524.77,3545.81) 6465.71,3545.81 cw(c6524.77,3545.81)
  circle w0.1: c6524.77,3545.81 r59.05
  region: 6583.82,3545.81 cw(c6524.77,3545.81) 6465.71,3545.81 cw(c6524.77,3545.81)
  region: 3344.59,3847.28 cw(c3285.54,3847.28) 3226.48,3847.28 cw(c3285.54,3847.28)
  circle w0.1: c3285.54,3847.28 r59.05
  region: 3344.59,3847.28 cw(c3285.54,3847.28) 3226.48,3847.28 cw(c3285.54,3847.28)
  lines w10: 4280.67,4568.85 cw(c4280.67,5277.51) 4126.62,4585.79 ccw(c4083.82,4393.65) 3886.98,4393.65 3886.97,4240.97 cw(c3690.12,4240.97) 3690.12,4044.12 3285.54,4044.12 ccw(c3285.54,3847.27) 3088.69,3847.27 3088.69,3387.74 ccw(c3285.54,3387.74) 3285.54,3190.89 6485.4,3190.89 ccw(c6485.4,3427.11) 6721.62,3427.11 6721.61,3545.8 ccw(c6524.77,3545.8) 6650.03,3697.65 cw(c6800.35,3879.87) 6650.03,4062.09 ccw(c6524.77,4213.94) 6721.62,4213.94 6721.61,4332.62 ccw(c6485.4,4332.62) 6485.4,4568.85 4280.68,4568.85

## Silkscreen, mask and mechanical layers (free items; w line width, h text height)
Top Silkscreen Layer:
  lines w7.87 net S$13491: 4563.13,3503.8 4590.53,3476.4 4850.43,3476.4 4878.03,3504 4878.03,3625.9 4850.33,3653.6 4602.43,3653.6 4590.63,3653.6 4563.13,3626.1 4563.13,3503.8
  lines w10 net S$23486: 4106.3,3629.92 4185.04,3629.92 4185.04,3712.6
  lines w10 net S$23490: 4165.35,3692.91 4185.04,3712.6
  lines w10 net S$23494: 4185.04,3712.6 4204.72,3692.91
  lines w10 net S$23502: 4106.3,3629.92 4129.92,3653.54
  lines w10 net S$23506: 4106.3,3629.92 4129.92,3606.3
  lines w10 net S$23513: 4185.04,3629.92 4224.41,3578.74
  lines w10 net S$23520: 4224.41,3578.74 4228.34,3606.3
  lines w10 net S$23524: 4196.85,3582.68 4224.41,3578.74
  text "X" at 4220.47,3681.1 h39.37
  text "Y" at 4066.93,3578.74 h39.37
  text "Z" at 4192.91,3515.75 h39.37
  text "COSTUM CTRLER 2026" at 5244.09,3421.26 h59.05
  text "HANDEL NODE V2" at 5251.97,3271.65 h98.42
Bottom Silkscreen Layer:
  circle w7.87: c3476.38,3606.3 r58.13
  circle w7.87: c3476.38,3346.46 r58.13
  text "A" at 3452.76,3566.93 h78.74
  text "B" at 3456.69,3303.15 h78.74
Mechanical Layer:
  circle w0.1: c6524.77,4213.94 r59.05
  circle w0.1: c6524.77,3545.81 r59.05
  circle w0.1: c3285.54,3847.28 r59.05

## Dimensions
4235.88,3832.72 to 4235.88,3803.15 on Document Layer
